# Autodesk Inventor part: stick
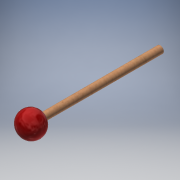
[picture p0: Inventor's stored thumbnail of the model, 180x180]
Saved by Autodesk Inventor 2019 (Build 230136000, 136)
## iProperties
Created: 2020-02
Part Number: stick
Material: Wood (Cherry)
Document SubType Name: Modeling
Designer: ash
Density: 0.63 g/cm^3
Appearance: Cherry - Natural Low Gloss
Author: ash
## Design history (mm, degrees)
sketch "Sketch1"
  geometry: L1 (0, 0)-(5, 0); L2 (5, 0)-(5, 165); L3 (0, 196.061)-(0, 0); L4 (0, -39.687)-(0, 238.12) reference; A1 r 15.752 centre (1.687, 180.4) between (5, 165) and (0, 196.061)
  constraints: 6 end point, 2 point on circle, 1 centre point, 1 horizontal, 1 perpendicular, 1 vertical
  dimensions: "d0" = 5 distance of L1.start L1.end; "d1" = 165 distance of L1.end L2.end
revolve "Revolution1" sketch "Sketch1" stored, may be unused: angle "d2" = 90 deg
body "Solid1"
